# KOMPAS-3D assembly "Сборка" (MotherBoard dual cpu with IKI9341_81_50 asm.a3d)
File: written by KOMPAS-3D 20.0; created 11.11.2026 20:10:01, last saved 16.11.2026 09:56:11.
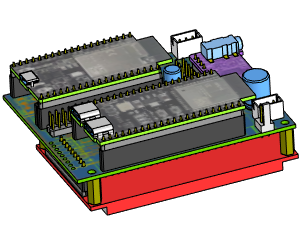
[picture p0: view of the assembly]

Document properties: Полное имя файла: D:\RicWork\Project-EPS32\box_compas\сборки компонентов\MotherBoard dual cpu with IKI9341_81_50 asm.a3d

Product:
- Part/product: Сборка
    Масса: 0.317065
  - Component [assembly]: Сборка  | Масса: 0.183959; source file: MotherBoard dual cpu asm.a3d
  - Component [assembly]: Сборка  | Масса: 0.133106; source file: ..\монитор\ILI9341_81_50 asm+ 9pin v2.a3d

Referenced files in D:\RicWork\Project-EPS32\box_compas\сборки компонентов\: MotherBoard dual cpu asm.a3d
Referenced files in D:\RicWork\Project-EPS32\box_compas\монитор\: ILI9341_81_50 asm+ 9pin v2.a3d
